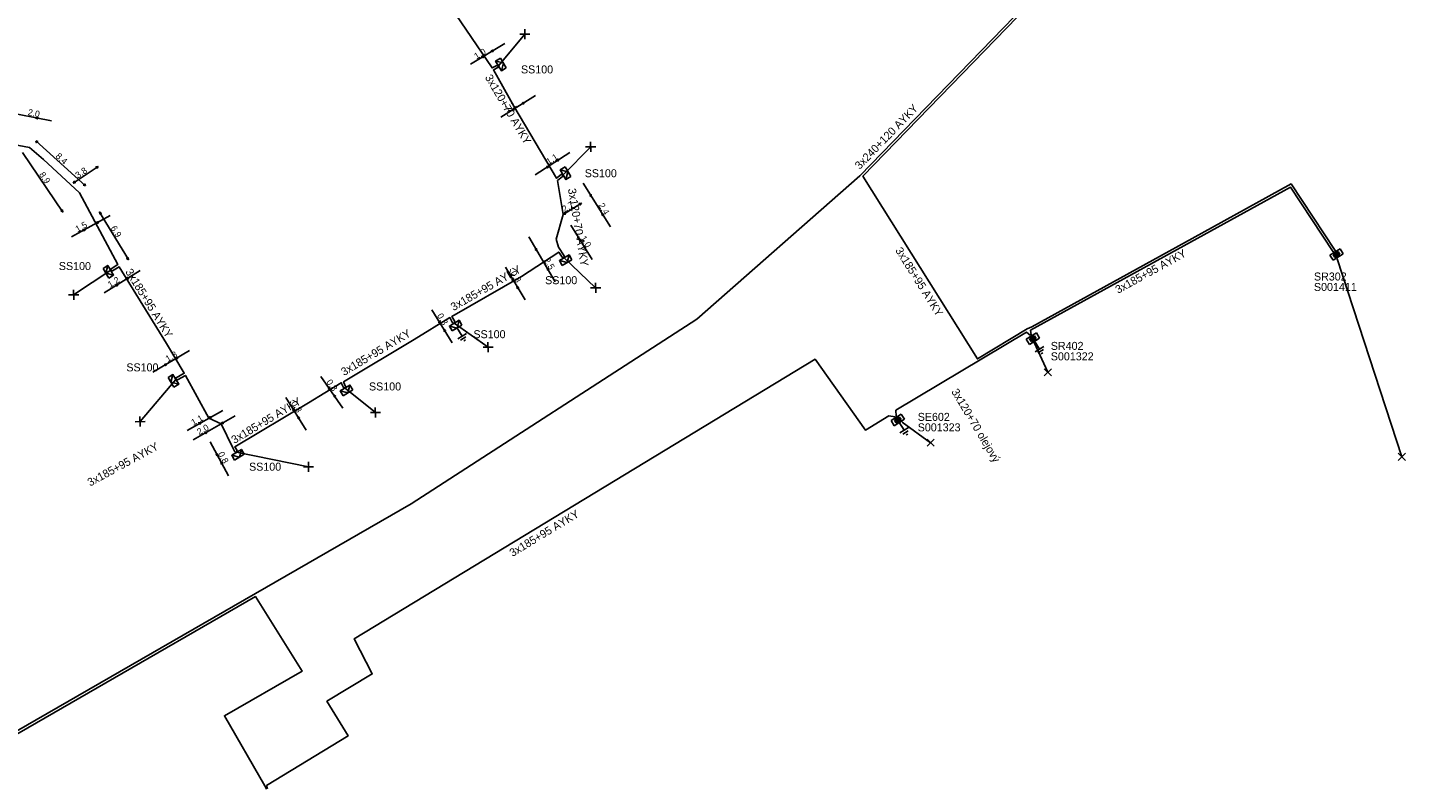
# Model space of a CAD drawing. Extents: x -762500 to -761285, y -1155006 to -1154135.
# Drawn here: x -761909.8 to -761738.6, y -1154857.3 to -1154763.7 of the extents above; entities that cross this region are included whole.
import ezdxf

# ---------------------------------------------------------------- set-up
doc = ezdxf.new("R2010")
doc.units = 0
for name, color, linetype in [('Vrstva 15', 7, 'Continuous'), ('Vrstva 28', 7, 'Continuous'), ('Vrstva 29', 7, 'Continuous'), ('Vrstva 30', 7, 'Continuous'), ('Vrstva 31', 7, 'Continuous'), ('Vrstva 33', 7, 'Continuous'), ('Vrstva 34', 7, 'Continuous'), ('Vrstva 40', 7, 'Continuous'), ('Vrstva 5', 7, 'Continuous'), ('Vrstva 59', 7, 'Continuous'), ('Vrstva 6', 7, 'Continuous')]:
    doc.layers.add(name, color=color, linetype=linetype)

msp = doc.modelspace()

# ---------------------------------------------------------------- linework, layer by layer
at = {"layer": 'Vrstva 15'}
for points in [[(-761856.436, -1154800.947), (-761855.793, -1154802.018)], [(-761855.257, -1154801.696), (-761856.328, -1154802.34)], [(-761855.304, -1154802.086), (-761855.979, -1154802.492)], [(-761855.471, -1154802.554), (-761855.581, -1154802.62)], [(-761855.357, -1154802.485), (-761855.471, -1154802.554)], [(-761784.707, -1154802.551), (-761784.045, -1154803.611)], [(-761783.515, -1154803.279), (-761784.575, -1154803.942)], [(-761783.555, -1154803.67), (-761784.223, -1154804.087)], [(-761783.714, -1154804.141), (-761783.822, -1154804.209)], [(-761783.601, -1154804.07), (-761783.714, -1154804.141)], [(-761801.507, -1154812.651), (-761800.845, -1154813.711)], [(-761800.315, -1154813.38), (-761801.375, -1154814.042)], [(-761800.355, -1154813.77), (-761801.023, -1154814.188)], [(-761800.514, -1154814.241), (-761800.622, -1154814.309)], [(-761800.401, -1154814.17), (-761800.514, -1154814.241)]]:
    msp.add_lwpolyline(points, dxfattribs=at)
at = {"layer": 'Vrstva 28'}
for points in [[(-761746.674, -1154791.149), (-761747.946, -1154791.943)], [(-761747.946, -1154791.943), (-761747.549, -1154792.579)], [(-761747.549, -1154792.579), (-761746.277, -1154791.785)], [(-761746.903, -1154791.507), (-761747.534, -1154791.902)], [(-761747.534, -1154791.902), (-761747.334, -1154792.222)], [(-761746.918, -1154791.572), (-761747.469, -1154791.917)], [(-761747.469, -1154791.917), (-761747.319, -1154792.157)], [(-761746.933, -1154791.637), (-761747.404, -1154791.932)], [(-761747.404, -1154791.932), (-761747.304, -1154792.092)], [(-761746.948, -1154791.703), (-761747.339, -1154791.947)], [(-761747.339, -1154791.947), (-761747.289, -1154792.027)], [(-761747.334, -1154792.222), (-761746.703, -1154791.828)], [(-761747.319, -1154792.157), (-761746.768, -1154791.813)], [(-761747.304, -1154792.092), (-761746.833, -1154791.798)], [(-761747.289, -1154792.027), (-761746.898, -1154791.783)], [(-761747.279, -1154791.965), (-761746.958, -1154791.765)], [(-761746.898, -1154791.783), (-761746.948, -1154791.703)], [(-761746.833, -1154791.798), (-761746.933, -1154791.637)], [(-761746.768, -1154791.813), (-761746.918, -1154791.572)], [(-761746.703, -1154791.828), (-761746.903, -1154791.507)], [(-761746.277, -1154791.785), (-761746.674, -1154791.149)], [(-761784.415, -1154801.609), (-761785.687, -1154802.403)], [(-761785.289, -1154803.04), (-761784.017, -1154802.245)], [(-761784.643, -1154801.967), (-761785.274, -1154802.362)], [(-761784.658, -1154802.032), (-761785.209, -1154802.377)], [(-761784.673, -1154802.097), (-761785.144, -1154802.392)], [(-761784.688, -1154802.163), (-761785.079, -1154802.407)], [(-761785.044, -1154802.552), (-761784.573, -1154802.258)], [(-761785.029, -1154802.487), (-761784.638, -1154802.243)], [(-761785.019, -1154802.425), (-761784.698, -1154802.225)], [(-761784.638, -1154802.243), (-761784.688, -1154802.163)], [(-761784.573, -1154802.258), (-761784.673, -1154802.097)], [(-761784.508, -1154802.273), (-761784.658, -1154802.032)], [(-761784.443, -1154802.288), (-761784.643, -1154801.967)], [(-761784.017, -1154802.245), (-761784.415, -1154801.609)], [(-761785.687, -1154802.403), (-761785.289, -1154803.04)], [(-761785.274, -1154802.362), (-761785.074, -1154802.682)], [(-761785.209, -1154802.377), (-761785.059, -1154802.617)], [(-761785.144, -1154802.392), (-761785.044, -1154802.552)], [(-761785.079, -1154802.407), (-761785.029, -1154802.487)], [(-761785.074, -1154802.682), (-761784.443, -1154802.288)], [(-761785.059, -1154802.617), (-761784.508, -1154802.273)], [(-761801.214, -1154811.708), (-761802.486, -1154812.503)], [(-761802.486, -1154812.503), (-761802.088, -1154813.139)], [(-761802.088, -1154813.139), (-761800.816, -1154812.345)], [(-761801.442, -1154812.067), (-761802.073, -1154812.461)], [(-761802.073, -1154812.461), (-761801.873, -1154812.782)], [(-761801.457, -1154812.132), (-761802.008, -1154812.476)], [(-761802.008, -1154812.476), (-761801.858, -1154812.717)], [(-761801.472, -1154812.197), (-761801.943, -1154812.492)], [(-761801.943, -1154812.492), (-761801.843, -1154812.652)], [(-761801.487, -1154812.262), (-761801.878, -1154812.507)], [(-761801.878, -1154812.507), (-761801.828, -1154812.587)], [(-761801.873, -1154812.782), (-761801.242, -1154812.388)], [(-761801.858, -1154812.717), (-761801.307, -1154812.373)], [(-761801.843, -1154812.652), (-761801.372, -1154812.358)], [(-761801.828, -1154812.587), (-761801.437, -1154812.343)], [(-761801.818, -1154812.525), (-761801.497, -1154812.324)], [(-761801.437, -1154812.343), (-761801.487, -1154812.262)], [(-761801.372, -1154812.358), (-761801.472, -1154812.197)], [(-761801.307, -1154812.373), (-761801.457, -1154812.132)], [(-761801.242, -1154812.388), (-761801.442, -1154812.067)], [(-761800.816, -1154812.345), (-761801.214, -1154811.708)]]:
    msp.add_lwpolyline(points, dxfattribs=at)
at = {"layer": 'Vrstva 31'}
for points in [[(-761850.298, -1154768.671), (-761850.898, -1154769.032), (-761851.619, -1154767.832), (-761851.019, -1154767.471)], [(-761850.658, -1154768.071), (-761851.619, -1154767.832)], [(-761850.298, -1154768.671), (-761851.019, -1154767.471)], [(-761850.658, -1154768.071), (-761850.898, -1154769.032)], [(-761842.278, -1154782.192), (-761842.878, -1154782.552), (-761843.599, -1154781.352), (-761842.999, -1154780.992)], [(-761842.638, -1154781.592), (-761843.599, -1154781.352)], [(-761842.278, -1154782.192), (-761842.999, -1154780.992)], [(-761842.638, -1154781.592), (-761842.878, -1154782.552)], [(-761843.332, -1154793.232), (-761843.693, -1154792.632), (-761842.493, -1154791.911), (-761842.132, -1154792.511)], [(-761842.732, -1154792.872), (-761842.493, -1154791.911)], [(-761900.412, -1154793.588), (-761899.812, -1154793.227), (-761899.091, -1154794.427), (-761899.691, -1154794.788)], [(-761900.412, -1154793.588), (-761899.691, -1154794.788)], [(-761900.052, -1154794.188), (-761899.812, -1154793.227)], [(-761842.732, -1154792.872), (-761843.693, -1154792.632)], [(-761843.332, -1154793.232), (-761842.132, -1154792.511)], [(-761900.052, -1154794.188), (-761899.091, -1154794.427)], [(-761857.011, -1154801.363), (-761857.372, -1154800.763), (-761856.172, -1154800.042), (-761855.811, -1154800.642)], [(-761856.411, -1154801.002), (-761856.172, -1154800.042)], [(-761856.411, -1154801.002), (-761857.372, -1154800.763)], [(-761857.011, -1154801.363), (-761855.811, -1154800.642)], [(-761892.323, -1154807.148), (-761891.723, -1154806.787), (-761891.002, -1154807.987), (-761891.602, -1154808.348)], [(-761892.323, -1154807.148), (-761891.602, -1154808.348)], [(-761891.962, -1154807.748), (-761891.723, -1154806.787)], [(-761891.962, -1154807.748), (-761891.002, -1154807.987)], [(-761870.572, -1154809.422), (-761870.932, -1154808.822), (-761869.732, -1154808.101), (-761869.372, -1154808.701)], [(-761869.972, -1154809.062), (-761870.932, -1154808.822)], [(-761870.572, -1154809.422), (-761869.372, -1154808.701)], [(-761869.972, -1154809.062), (-761869.732, -1154808.101)], [(-761884.052, -1154817.402), (-761884.412, -1154816.802), (-761883.212, -1154816.081), (-761882.852, -1154816.681)], [(-761883.452, -1154817.042), (-761884.412, -1154816.802)], [(-761884.052, -1154817.402), (-761882.852, -1154816.681)], [(-761883.452, -1154817.042), (-761883.212, -1154816.081)]]:
    msp.add_lwpolyline(points, dxfattribs=at)
at = {"layer": 'Vrstva 34'}
for points in [[(-761848.625, -1154764.511), (-761847.375, -1154764.489)], [(-761847.989, -1154765.125), (-761848.011, -1154763.875)], [(-761839.799, -1154779.125), (-761839.821, -1154777.875)], [(-761840.435, -1154778.511), (-761839.185, -1154778.489)], [(-761839.179, -1154796.625), (-761839.201, -1154795.375)], [(-761904.685, -1154796.891), (-761903.435, -1154796.869)], [(-761904.049, -1154797.505), (-761904.071, -1154796.255)], [(-761839.815, -1154796.011), (-761838.565, -1154795.989)], [(-761853.185, -1154803.391), (-761851.935, -1154803.369)], [(-761852.549, -1154804.005), (-761852.571, -1154802.755)], [(-761783.442, -1154806.058), (-761782.558, -1154806.942)], [(-761783.442, -1154806.942), (-761782.558, -1154806.058)], [(-761895.799, -1154813.255), (-761895.821, -1154812.005)], [(-761867.185, -1154811.511), (-761865.935, -1154811.489)], [(-761866.549, -1154812.125), (-761866.571, -1154810.875)], [(-761896.435, -1154812.641), (-761895.185, -1154812.619)], [(-761798.002, -1154814.808), (-761797.118, -1154815.692)], [(-761798.002, -1154815.692), (-761797.118, -1154814.808)], [(-761874.869, -1154818.875), (-761874.891, -1154817.625)], [(-761739.442, -1154816.558), (-761738.558, -1154817.442)], [(-761739.442, -1154817.442), (-761738.558, -1154816.558)], [(-761875.505, -1154818.261), (-761874.255, -1154818.239)]]:
    msp.add_lwpolyline(points, dxfattribs=at)
at = {"layer": 'Vrstva 40'}
for points in [[(-761850.49, -1154765.67), (-761854.74, -1154768.23)], [(-761846.66, -1154772.13), (-761850.96, -1154774.81)], [(-761912.72, -1154774.09), (-761906.83, -1154775.26)], [(-761908.77, -1154777.75), (-761902.57, -1154783.35)], [(-761910.4, -1154779.18), (-761905.39, -1154786.59)], [(-761846.69, -1154781.97), (-761842.39, -1154779.19)], [(-761904.13, -1154783), (-761901.01, -1154780.92)], [(-761840.74, -1154783), (-761837.36, -1154788.44)], [(-761897.26, -1154792.51), (-761900.84, -1154786.59)], [(-761843.24, -1154786.91), (-761840.96, -1154785.49)], [(-761899.51, -1154787.04), (-761904.34, -1154789.69)], [(-761842.28, -1154788.24), (-761839.61, -1154792.51)], [(-761847.51, -1154789.68), (-761844.21, -1154795.27)], [(-761847.96, -1154797.52), (-761850.41, -1154793.45)], [(-761895.79, -1154793.87), (-761900.26, -1154796.62)], [(-761857.01, -1154802.84), (-761859.54, -1154798.74)], [(-761894.21, -1154806.47), (-761889.65, -1154803.81)], [(-761870.6, -1154810.95), (-761873.33, -1154807.02)], [(-761875.15, -1154813.71), (-761877.69, -1154809.62)], [(-761885.52, -1154811.24), (-761889.95, -1154813.72)], [(-761883.99, -1154811.92), (-761889.21, -1154814.89)], [(-761887.1, -1154815.15), (-761884.8, -1154819.37)]]:
    msp.add_lwpolyline(points, dxfattribs=at)
for points in [[(-761853.028, -1154767.199), (-761853.183, -1154767.419), (-761853.294, -1154767.242)], [(-761852.202, -1154766.701), (-761852.047, -1154766.481), (-761851.936, -1154766.658)], [(-761848.362, -1154773.191), (-761848.207, -1154772.971), (-761848.096, -1154773.148)], [(-761908.793, -1154774.87), (-761908.529, -1154774.815), (-761908.569, -1154775.02)], [(-761849.258, -1154773.749), (-761849.413, -1154773.969), (-761849.524, -1154773.792)], [(-761908.771, -1154777.748), (-761908.517, -1154777.837), (-761908.656, -1154777.992)], [(-761901.008, -1154780.918), (-761901.156, -1154781.144), (-761901.273, -1154780.971)], [(-761845.008, -1154780.878), (-761845.16, -1154781.101), (-761845.273, -1154780.926)], [(-761844.072, -1154780.271), (-761843.921, -1154780.048), (-761843.807, -1154780.223)], [(-761904.132, -1154783.001), (-761903.985, -1154782.775), (-761903.868, -1154782.949)], [(-761902.568, -1154783.352), (-761902.822, -1154783.263), (-761902.683, -1154783.108)], [(-761839.688, -1154784.703), (-761839.909, -1154784.547), (-761839.732, -1154784.436)], [(-761905.389, -1154786.592), (-761905.617, -1154786.449), (-761905.446, -1154786.329)], [(-761900.841, -1154786.587), (-761900.621, -1154786.743), (-761900.798, -1154786.854)], [(-761843.242, -1154786.911), (-761843.087, -1154786.691), (-761842.976, -1154786.868)], [(-761840.958, -1154785.489), (-761841.113, -1154785.709), (-761841.224, -1154785.532)], [(-761838.421, -1154786.738), (-761838.2, -1154786.893), (-761838.378, -1154787.004)], [(-761901.262, -1154788.001), (-761901.096, -1154787.789), (-761900.994, -1154787.972)], [(-761902.588, -1154788.729), (-761902.754, -1154788.941), (-761902.856, -1154788.758)], [(-761841.219, -1154789.943), (-761841.442, -1154789.791), (-761841.267, -1154789.677)], [(-761846.488, -1154791.402), (-761846.706, -1154791.243), (-761846.527, -1154791.135)], [(-761840.671, -1154790.808), (-761840.448, -1154790.96), (-761840.624, -1154791.073)], [(-761897.259, -1154792.512), (-761897.479, -1154792.357), (-761897.302, -1154792.246)], [(-761845.231, -1154793.547), (-761845.013, -1154793.707), (-761845.192, -1154793.814)], [(-761897.492, -1154794.921), (-761897.337, -1154794.701), (-761897.226, -1154794.878)], [(-761849.379, -1154795.162), (-761849.596, -1154795.003), (-761849.417, -1154794.895)], [(-761898.548, -1154795.569), (-761898.703, -1154795.789), (-761898.814, -1154795.612)], [(-761848.991, -1154795.808), (-761848.774, -1154795.967), (-761848.953, -1154796.075)], [(-761858.489, -1154800.442), (-761858.709, -1154800.287), (-761858.532, -1154800.176)], [(-761858.061, -1154801.138), (-761857.841, -1154801.293), (-761858.018, -1154801.404)], [(-761892.478, -1154805.459), (-761892.637, -1154805.676), (-761892.745, -1154805.497)], [(-761891.382, -1154804.821), (-761891.223, -1154804.603), (-761891.115, -1154804.783)], [(-761872.189, -1154808.662), (-761872.417, -1154808.519), (-761872.246, -1154808.399)], [(-761871.741, -1154809.308), (-761871.513, -1154809.452), (-761871.684, -1154809.571)], [(-761887.272, -1154812.221), (-761887.109, -1154812.006), (-761887.005, -1154812.187)], [(-761876.629, -1154811.323), (-761876.849, -1154811.167), (-761876.672, -1154811.056)], [(-761876.201, -1154812.008), (-761875.981, -1154812.164), (-761876.158, -1154812.274)], [(-761888.198, -1154812.739), (-761888.361, -1154812.954), (-761888.465, -1154812.773)], [(-761887.468, -1154813.899), (-761887.631, -1154814.114), (-761887.735, -1154813.933)], [(-761885.732, -1154812.911), (-761885.569, -1154812.696), (-761885.465, -1154812.877)], [(-761886.149, -1154816.912), (-761886.361, -1154816.745), (-761886.178, -1154816.644)], [(-761885.761, -1154817.608), (-761885.549, -1154817.775), (-761885.732, -1154817.876)]]:
    msp.add_lwpolyline(points, close=True, dxfattribs=at)
at = {"layer": 'Vrstva 5'}
for points in [[(-761793.37, -1154751.76), (-761793.05, -1154752.07), (-761787.15, -1154762.31), (-761806.36, -1154782.09), (-761826.62, -1154799.89), (-761862.11, -1154822.83), (-761911.18, -1154851.08), (-761920.77, -1154856.64), (-761929.42, -1154842.63), (-761938.89, -1154848.44), (-761944.86, -1154847.05), (-761973.05, -1154830.1), (-761980.58, -1154827.44), (-761983.64, -1154827.88), (-761985.29, -1154827.77), (-762002.6, -1154821.09), (-762002.75, -1154820.78), (-762006.65, -1154819.22), (-762005.33, -1154816.4)], [(-761747.33, -1154791.4), (-761747.29, -1154791.37), (-761752.76, -1154783.1), (-761763.87, -1154789.21), (-761784.99, -1154800.86), (-761785.56, -1154801.09), (-761791.75, -1154804.84), (-761805.98, -1154782.13), (-761786.78, -1154762.36), (-761792.86, -1154751.8), (-761793.44, -1154751.65)], [(-761843.09, -1154792.27), (-761843.09, -1154792.02), (-761843.8, -1154790.97), (-761844.09, -1154789.98), (-761843.24, -1154786.91), (-761843.94, -1154782.69), (-761843.29, -1154782.19), (-761843.24, -1154781.95), (-761843.46, -1154781.93), (-761844.05, -1154782.39), (-761849.36, -1154773.42), (-761851.9, -1154768.93), (-761851.34, -1154768.64), (-761851.26, -1154768.43), (-761851.47, -1154768.37), (-761852.06, -1154768.68), (-761859.12, -1154758.22)], [(-761921.81, -1154784.8), (-761921.75, -1154784.6), (-761922.17, -1154783.92), (-761913.09, -1154778.7), (-761911.53, -1154778.2), (-761909.53, -1154778.59), (-761907.79, -1154780.05), (-761903.33, -1154784.19), (-761898.58, -1154793.13), (-761899.39, -1154793.63), (-761899.45, -1154793.83)], [(-761785.06, -1154801.86), (-761785.14, -1154801.28), (-761752.86, -1154783.49), (-761747.53, -1154791.52), (-761747.44, -1154791.47)], [(-761899.45, -1154793.83), (-761899.24, -1154793.88), (-761898.42, -1154793.39), (-761892.53, -1154802.92), (-761890.32, -1154806.63), (-761891.31, -1154807.19), (-761891.36, -1154807.39), (-761891.14, -1154807.44), (-761890.18, -1154806.89), (-761887.27, -1154812.22), (-761885.73, -1154812.91), (-761884.28, -1154815.89), (-761884.02, -1154816.38), (-761883.81, -1154816.44), (-761883.75, -1154816.22), (-761884.02, -1154815.75), (-761874.87, -1154810.28), (-761870.8, -1154807.81), (-761870.53, -1154808.39), (-761870.33, -1154808.46), (-761870.26, -1154808.25), (-761870.52, -1154807.69), (-761861.75, -1154802.44), (-761857.31, -1154799.71), (-761856.98, -1154800.35), (-761856.77, -1154800.4), (-761856.71, -1154800.18), (-761857.05, -1154799.57), (-761848.4, -1154794.59), (-761843.78, -1154791.56), (-761843.34, -1154792.19), (-761843.09, -1154792.27)], [(-761801.86, -1154811.97), (-761801.88, -1154811.22), (-761785.65, -1154801.52), (-761785.17, -1154801.93)], [(-761879.97, -1154858.24), (-761880.08, -1154857.83), (-761869.96, -1154851.69), (-761872.58, -1154847.37), (-761866.96, -1154843.98), (-761869.19, -1154839.6), (-761811.93, -1154804.88), (-761805.65, -1154813.7), (-761802.76, -1154811.9), (-761801.97, -1154812.04)], [(-762005.61, -1154816.29), (-762007.05, -1154819.38), (-762002.97, -1154821.02), (-762002.81, -1154821.33), (-761985.36, -1154828.06), (-761983.62, -1154828.19), (-761980.61, -1154827.74), (-761973.18, -1154830.37), (-761944.98, -1154847.33), (-761938.84, -1154848.76), (-761929.52, -1154843.04), (-761920.87, -1154857.05), (-761881.47, -1154834.36), (-761875.67, -1154843.65), (-761885.32, -1154849.18), (-761880.3, -1154857.9), (-761880.08, -1154858.31)]]:
    msp.add_lwpolyline(points, dxfattribs=at)
at = {"layer": 'Vrstva 59'}
for points in [[(-761851.26, -1154768.43), (-761848, -1154764.5)], [(-761843.24, -1154781.95), (-761839.81, -1154778.5)], [(-761843.09, -1154792.27), (-761839.19, -1154796)], [(-761747.03, -1154792.41), (-761739, -1154817)], [(-761899.45, -1154793.83), (-761904.06, -1154796.88)], [(-761856.77, -1154800.4), (-761852.56, -1154803.38)], [(-761784.68, -1154802.81), (-761783, -1154806.5)], [(-761891.36, -1154807.39), (-761895.81, -1154812.63)], [(-761870.33, -1154808.46), (-761866.56, -1154811.5)], [(-761801.08, -1154812.68), (-761797.56, -1154815.25)], [(-761883.81, -1154816.44), (-761874.88, -1154818.25)]]:
    msp.add_lwpolyline(points, dxfattribs=at)

# ---------------------------------------------------------------- texts
at = {"layer": 'Vrstva 29'}
for s, p in [('S001411', (-761749.93, -1154796.4)), ('S001322', (-761782.63, -1154805.02)), ('S001323', (-761799.17, -1154813.84))]:
    msp.add_text(s, height=0.9943, dxfattribs=at).set_placement(p)
at = {"layer": 'Vrstva 30'}
for s, p in [('SR302', (-761749.93, -1154795.1)), ('SR402', (-761782.63, -1154803.72)), ('SE602', (-761799.17, -1154812.54))]:
    msp.add_text(s, height=0.9943, dxfattribs=at).set_placement(p)
at = {"layer": 'Vrstva 33'}
for p in [(-761848.47, -1154769.37), (-761840.55, -1154782.27), (-761905.9, -1154793.8), (-761845.47, -1154795.56), (-761854.38, -1154802.27), (-761897.51, -1154806.39), (-761867.36, -1154808.76), (-761882.26, -1154818.73)]:
    msp.add_text('SS100', height=0.9943, dxfattribs=at).set_placement(p)
at = {"layer": 'Vrstva 40'}
for s, rotation, p in [('1,0', 31.06764, (-761854, -1154767.65)), ('1,1', 31.89064, (-761850.22, -1154774.21)), ('2,0', 348.70676, (-761909.8, -1154774.55)), ('8,4', 317.91089, (-761906.37, -1154779.75)), ('1,1', 32.98323, (-761845.02, -1154780.75)), ('8,9', 304.06287, (-761908.39, -1154781.94)), ('3,8', 33.81672, (-761903.52, -1154782.45)), ('2,7', 31.91464, (-761843.06, -1154786.66)), ('2,4', 301.90376, (-761838.88, -1154785.77)), ('1,5', 28.76046, (-761903.58, -1154789.13)), ('6,9', 301.16234, (-761899.5, -1154788.58)), ('1,0', 302.0847, (-761841.13, -1154789.85)), ('2,5', 300.61947, (-761845.66, -1154792.57)), ('1,2', 31.51773, (-761899.52, -1154796.02)), ('0,8', 300.95979, (-761849.82, -1154794.19)), ('0,8', 301.56175, (-761858.94, -1154799.47)), ('1,3', 30.19054, (-761892.36, -1154805.25)), ('0,8', 304.69656, (-761872.7, -1154807.72)), ('0,8', 301.93115, (-761877.09, -1154810.36)), ('1,1', 29.21511, (-761889.18, -1154813.15)), ('2,0', 29.63688, (-761888.45, -1154814.32)), ('0,8', 298.56536, (-761886.16, -1154816.63))]:
    msp.add_text(s, height=0.7954, rotation=rotation, dxfattribs=at).set_placement(p)
at = {"layer": 'Vrstva 6'}
for s, height, rotation, p in [('3x120+70 AYKY', 0.99429, 300.63753, (-761852.99, -1154769.86)), ('3x240+120 AYKY', 0.99429, 45.83606, (-761806.38, -1154781.37)), ('3x120+70 AYKY', 0.99429, 279.39185, (-761842.64, -1154783.73)), ('3x185+95 AYKY', 0.99429, 302.07835, (-761802, -1154791.36)), ('3x185+95 AYKY', 0.99429, 28.8595, (-761774.27, -1154796.76)), ('3x185+95 AYKY', 0.99429, 301.72843, (-761897.68, -1154794.01)), ('3x185+95 AYKY', 0.99428, 29.93076, (-761856.85, -1154798.91)), ('3x185+95 AYKY', 0.99429, 30.88014, (-761870.46, -1154806.98)), ('3x120+70 olejový', 0.99428, 300.87544, (-761795.03, -1154808.9)), ('3x185+95 AYKY', 0.99428, 30.86787, (-761884.09, -1154815.42)), ('3x185+95 AYKY', 0.99429, 28.59991, (-761902.01, -1154820.71)), ('3x185+95 AYKY', 0.99429, 31.23403, (-761849.52, -1154829.46))]:
    msp.add_text(s, height=height, rotation=rotation, dxfattribs=at).set_placement(p)

doc.saveas('drawing.dxf')
